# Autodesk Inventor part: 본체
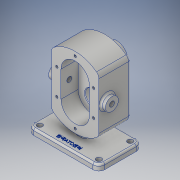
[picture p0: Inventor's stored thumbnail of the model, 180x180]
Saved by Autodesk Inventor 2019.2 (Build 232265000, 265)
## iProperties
Created: 2019-03
Part Number: 본체
Material: 알루미늄 6061
Document SubType Name: Modeling
Designer: User
Density: 2.7 g/cm^3
Appearance: 알루미늄 - 평지
Mass: 1187.12 g
Surface Area: 719.257 cm^2
Volume: 439.673 cm^3
Author: User
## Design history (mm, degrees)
sketch "스케치1"
  geometry: L1 (60, 36.5)-(-60, 36.5); L2 (-60, 36.5)-(-60, -36.5); L3 (-60, -36.5)-(60, -36.5); L4 (60, -36.5)-(60, 36.5); L5 (0, -51.1)-(0, 51.1) reference; L6 (-84, 0)-(84, 0) reference; 1 further point
  constraints: 8 end point, 2 parallel, 1 horizontal, 1 perpendicular, 2 other
  dimensions: "d0" = 120 distance of L2.end L3.end; "d1" = 73 distance of L1.end L2.end
extrude "돌출1" new body sketch "스케치1" distance "d2" = 10; taper "d3" = 0 deg
sketch "스케치3"
  geometry: L1 (20, 122.721)-(100, 122.721); L2 (100, 122.721)-(100, 33.279); L3 (100, 33.279)-(20, 33.279); L4 (20, 33.279)-(20, 122.721); L5 (60, -27.6)-(60, 165.6) reference; L6 (-24, 0)-(144, 0) reference; A1 r 60 centre (60, 78) between (100, 122.721) and (20, 122.721); A2 r 60 centre (60, 78) between (20, 33.279) and (100, 33.279); 1 further point
  constraints: 8 end point, 4 point on circle, 2 centre point, 2 parallel, 1 coincident, 1 horizontal, 1 perpendicular, 1 other
  dimensions: "d9" = 60 radius of A2; "d10" = 60 radius of A1; "d11" = 138 dimension on A1 L6; "d23" = 80 distance between parallel lines of L2 L4
extrude "돌출2" join sketch "스케치3" distance "d12" = 53; taper "d13" = 0 deg
sketch "스케치4"
  geometry: L1 (50, 6.5)-(0, 6.5); L2 (0, 6.5)-(0, -36.5); L3 (0, -36.5)-(50, -36.5); L4 (50, -36.5)-(50, 6.5); L5 (0, 36.5)-(0, -36.5) reference; L6 (0, -36.5)-(10, -36.5) reference; 1 further point
  constraints: 8 end point, 2 collinear, 2 parallel, 1 horizontal, 1 perpendicular
  dimensions: "d14" = 43 distance of L3.end L1.start; "d15" = 50 distance of L2.end L3.end
extrude "돌출3" join sketch "스케치4" stored distance "d16" = 12; taper "d17" = 0 deg
sketch "스케치5"
  geometry: L1 (0, 36.5)-(0, -36.5) reference; L2 (122.721, -36.5)-(33.279, -36.5) reference; L3 (33.279, 16.5)-(122.721, 16.5) reference; C1 r 11 at (78, 2.5); 1 further point
  constraints: 1 centre point
  dimensions: "d18" = 22 diameter of C1; "d19" = 78 distance from line of C1.centre L1; "d104" = 14 distance from line of L3 C1.centre
extrude "돌출4" join sketch "스케치5" stored distance "d21" = 96; taper "d22" = 0 deg
sketch "스케치6"
  geometry: L1 (-60, 100)-(-60, 56); L2 (-84, 100)-(-84, 56); L3 (-36, 56)-(-36, 100); L4 (-60, 174.383)-(-60, -45.544) reference; L5 (-144, 0)-(24, 0) reference; A1 r 24 centre (-60, 100) between (-36, 100) and (-84, 100); A2 r 24 centre (-60, 56) between (-84, 56) and (-36, 56); 2 further points
  constraints: 8 end point, 4 point on circle, 4 tangent, 2 centre point, 1 collinear, 1 midpoint, 1 parallel, 1 vertical
  dimensions: "d24" = 24 radius of A1; "d25" = 44 distance of L1.start L1.end; "d26" = 78 distance from line of L5 point (-60, 78)
extrude "돌출5" cut sketch "스케치6" distance "d27" = 29; taper "d28" = 0 deg
sketch "스케치7"
  geometry: L1 (60, 0)-(60, 192.078); L2 (0, 0)-(120, 0) reference; C1 r 19 at (60, 100)
  constraints: 2 end point, 1 centre point, 1 point on line, 1 vertical
  dimensions: "d29" = 38 diameter of C1; "d30" = 100 distance from line of L2 C1.centre
extrude "돌출6" join sketch "스케치7" distance "d31" = 17; taper "d32" = 0 deg
sketch "스케치8"
  geometry: C1 r 19 at (0, 0) reference; 2 further points
  constraints: 1 coincident
hole "구멍1" sketch "스케치8" at (0, 0) diameter "d33" = 17; stored, may be unused: countersink angle "d37" = 90 deg, drill point angle "d39" = 0 deg; dims "d34" = 6, "d35" = 28, "d36" = 7.3, "d38" = 26
sketch "스케치9"
  geometry: L1 (-60, 26.459)-(-60, 107.532); L2 (-120, 0)-(0, 0) reference; 4 further points
  constraints: 3 point on line, 2 end point, 1 midpoint, 1 vertical
  dimensions: "d40" = 44 distance of point (-60, 56) point (-60, 100); "d41" = 100 distance from line of L2 point (-60, 100)
hole "구멍2" sketch "스케치9" at (-60, 100), (-60, 56) diameter "d42" = 25; stored, may be unused: countersink angle "d46" = 90 deg, drill point angle "d48" = 0 deg; dims "d43" = 6, "d44" = 28, "d45" = 7.3, "d47" = 15
sketch "스케치10"
  geometry: C1 r 11 at (0, 0) reference; 2 further points
  constraints: 1 coincident
hole "구멍3" sketch "스케치10" at (0, 0) diameter "d49" = 8.376; stored, may be unused: countersink angle "d53" = 90 deg, drill point angle "d55" = 0 deg; dims "d50" = 27, "d51" = 28, "d52" = 7.3, "d54" = 27
sketch "스케치11"
  geometry: C1 r 11 at (0, 0) reference; 2 further points
  constraints: 1 coincident
hole "구멍4" sketch "스케치11" at (0, 0) diameter "d56" = 8.376; stored, may be unused: countersink angle "d60" = 90 deg, drill point angle "d62" = 0 deg; dims "d57" = 27, "d58" = 28, "d59" = 7.3, "d61" = 27
sketch "스케치12"
  geometry: L1 (-60, 100)-(-60, 56); L2 (-91, 100)-(-91, 56); L3 (-29, 56)-(-29, 100); L4 (-60, 0)-(-60, 154.262); L5 (-120, 0)-(0, 0) reference; A1 r 31 centre (-60, 100) between (-29, 100) and (-91, 100); A2 r 31 centre (-60, 56) between (-91, 56) and (-29, 56); 9 further points
  constraints: 10 end point, 6 coincident, 6 point on circle, 4 tangent, 2 centre point, 2 vertical, 1 collinear, 1 midpoint, 1 parallel
  dimensions: "d65" = 31 radius of A1; "d66" = 56 distance from line of L5 L1.end; "d67" = 100 distance from line of L5 L1.start
hole "구멍5" sketch "스케치12" at (-60, 131), (-91, 100), (-91, 56), (-60, 25), (-29, 100), (-29, 56) diameter "d68" = 4.134; stored, may be unused: countersink angle "d72" = 90 deg, drill point angle "d74" = 118 deg; dims "d69" = 10, "d70" = 28, "d71" = 7.3, "d73" = 12
fillet "모깎기1" dims "d75" = 10
sketch "스케치13"
  geometry: A1 r 10 centre (-50, -26.5) between (-60, -26.5) and (-50, -36.5) reference; A2 r 10 centre (-50, 26.5) between (-50, 36.5) and (-60, 26.5) reference; A3 r 10 centre (50, -26.5) between (50, -36.5) and (60, -26.5) reference; A4 r 10 centre (50, 26.5) between (60, 26.5) and (50, 36.5) reference; 5 further points
  constraints: 4 coincident
hole "구멍6" sketch "스케치13" at (-50, -26.5), (-50, 26.5), (50, -26.5), (50, 26.5) diameter "d76" = 9; stored, may be unused: countersink angle "d80" = 90 deg, drill point angle "d82" = 0 deg; dims "d77" = 10, "d78" = 28, "d79" = 7.3, "d81" = 10
fillet "모깎기2" dims "d83" = 0.5
chamfer "모따기2" distance "d87" = 1; stored, may be unused: second distance "d88" = 2, angle "d89" = 30 deg
fillet "모깎기3" dims "d90" = 3
fillet "모깎기4" dims "d91" = 3
fillet "모깎기5" dims "d92" = 3
fillet "모깎기6" dims "d93" = 10
fillet "모깎기7" dims "d94" = 3
fillet "모깎기8" dims "d95" = 3
fillet "모깎기9" dims "d96" = 3
sketch "스케치14"
  geometry: L1 (-60, 26.5)-(-60, -26.5) reference; L2 (-50, -36.5)-(50, -36.5) reference; 2 further points
  constraints: 1 other
  dimensions: "d97" = 60 distance from line of L1 point (0, -26.5); "d98" = 10 distance from line of L2 point (0, -26.5)
feature "엠보싱1" sketch "스케치14" dims "d0" = 120, "d1" = 73, "d99" = 0.5, "d100" = 0
chamfer "모따기3" distance "d101" = 0.7; stored, may be unused: second distance "d102" = 2, angle "d103" = 30 deg
node "솔리드1"
